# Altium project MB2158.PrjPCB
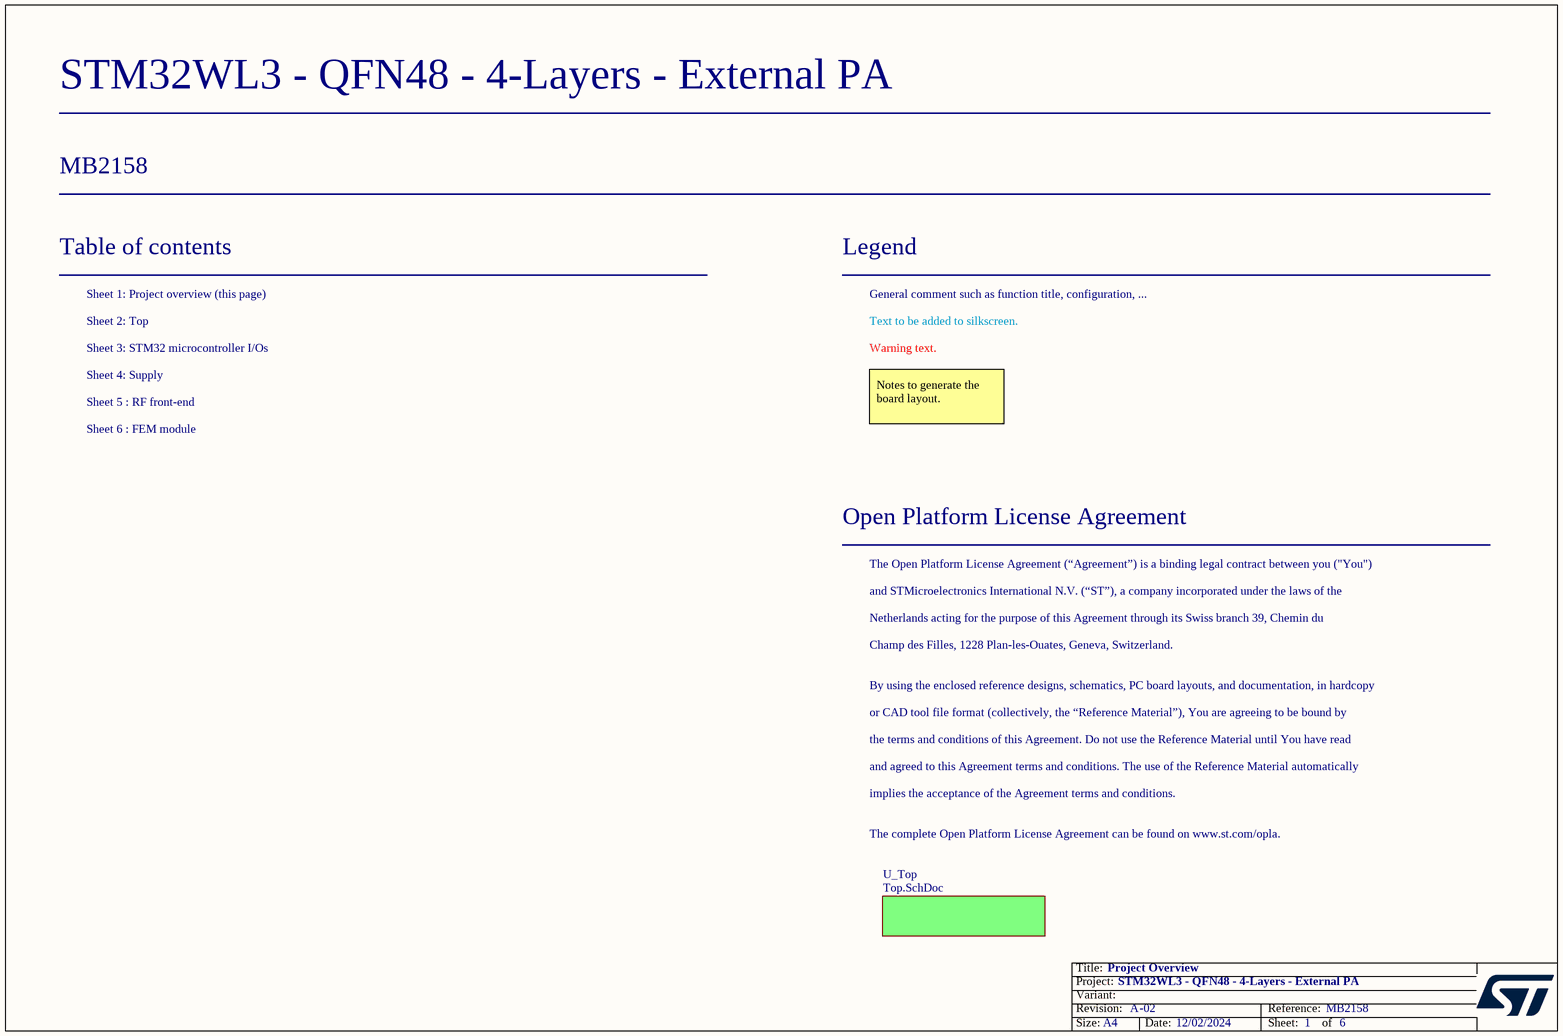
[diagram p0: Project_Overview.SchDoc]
Board_Assembly_Revision: 02; Board_Document_Date: 12/02/2024; Board_Name: STM32WL3 - QFN48 - 4-Layers - External PA; Board_PCB_Revision: A; Board_Reference: MB2158
6 sheets, 108 parts. Net scope: flat (ports and power ports of the same name join across sheets).
Board file: MB2158.PcbDoc
Sheets:
  Project_Overview.SchDoc
    U_Top = Top.SchDoc
      Designator = MCU_IOs.SchDoc
      Designator = RF.SchDoc
      Designator = Supply.SchDoc
      U_FEM = FEM.SchDoc

## Sheet Project_Overview.SchDoc: Project Overview
size A4; Date: Not used; ApprovedBy: Not used; CheckedBy: Not used; Author: Not used; CompanyName: STMicroelectronics; DrawnBy: Not used; Engineer: Not used; Organization: Not used; Address1: Not used; Address2: Not used; Address3: Not used; Address4: Not used; DocumentNumber: Not used; Revision: Not used; SheetNumber: 1; SheetTotal: 6

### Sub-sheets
U_Top = Top.SchDoc: no entries

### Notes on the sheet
- Table of contents
- Sheet 1: Project overview (this page)
- Legend
- General comment such as function title, configuration, ...
- Sheet 2: Top
- Sheet 3: STM32 microcontroller I/Os
- Sheet 4: Supply
- Text to be added to silkscreen.
- Warning text.
- Sheet 5 : RF front-end
- Sheet 6 : FEM module
- Notes to generate the board layout.
- Open Platform License Agreement
- The Open Platform License Agreement (“Agreement”) is a binding legal contract between you ("You")
- and STMicroelectronics International N.V. (“ST”), a company incorporated under the laws of the
- Netherlands acting for the purpose of this Agreement through its Swiss branch 39, Chemin du
- Champ des Filles, 1228 Plan-les-Ouates, Geneva, Switzerland.
- By using the enclosed reference designs, schematics, PC board layouts, and documentation, in hardcopy
- or CAD tool file format (collectively, the “Reference Material”), You are agreeing to be bound by
- the terms and conditions of this Agreement. Do not use the Reference Material until You have read
- and agreed to this Agreement terms and conditions. The use of the Reference Material automatically
- implies the acceptance of the Agreement terms and conditions.
- The complete Open Platform License Agreement can be found on www.st.com/opla.

## Sheet Top.SchDoc: Top Schematic
size A4; Date: Not used; ApprovedBy: Not used; CheckedBy: Not used; Author: Not used; CompanyName: STMicroelectronics; DrawnBy: Not used; Engineer: Not used; Organization: Not used; Address1: Not used; Address2: Not used; Address3: Not used; Address4: Not used; DocumentNumber: Not used; Revision: Not used; SheetNumber: 2; SheetTotal: 6
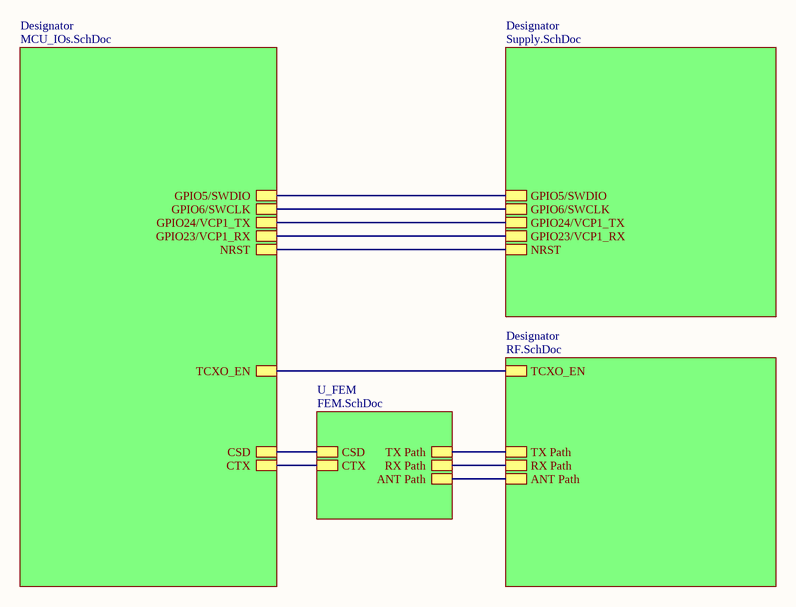
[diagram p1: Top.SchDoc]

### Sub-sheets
Designator = MCU_IOs.SchDoc: NRST, GPIO5/SWDIO, GPIO6/SWCLK, GPIO24/VCP1_TX, GPIO23/VCP1_RX, CTX, CSD, TCXO_EN
Designator = RF.SchDoc: RX Path, TX Path, ANT Path, TCXO_EN
Designator = Supply.SchDoc: NRST, GPIO5/SWDIO, GPIO6/SWCLK, GPIO23/VCP1_RX, GPIO24/VCP1_TX
U_FEM = FEM.SchDoc: TX Path, RX Path, CSD, CTX, ANT Path

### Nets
(unnamed): sheet Designator/NRST, sheet Designator/NRST
(unnamed): sheet Designator/GPIO5/SWDIO, sheet Designator/GPIO5/SWDIO  [a separate net that carries the same name]
(unnamed): sheet Designator/GPIO6/SWCLK, sheet Designator/GPIO6/SWCLK  [a separate net that carries the same name]
(unnamed): sheet Designator/GPIO24/VCP1_TX, sheet Designator/GPIO24/VCP1_TX  [a separate net that carries the same name]
(unnamed): sheet Designator/GPIO23/VCP1_RX, sheet Designator/GPIO23/VCP1_RX  [a separate net that carries the same name]
(unnamed): sheet Designator/CTX, sheet U_FEM/CTX  [a separate net that carries the same name]
(unnamed): sheet Designator/CSD, sheet U_FEM/CSD  [a separate net that carries the same name]
(unnamed): sheet Designator/TCXO_EN, sheet Designator/TCXO_EN  [a separate net that carries the same name]
(unnamed): sheet Designator/RX Path, sheet U_FEM/RX Path  [a separate net that carries the same name]
(unnamed): sheet Designator/TX Path, sheet U_FEM/TX Path  [a separate net that carries the same name]
(unnamed): sheet Designator/ANT Path, sheet U_FEM/ANT Path  [a separate net that carries the same name]

## Sheet MCU_IOs.SchDoc: STM32 I/Os & Clock
size A4; Date: Not used; ApprovedBy: Not used; CheckedBy: Not used; Author: Not used; CompanyName: STMicroelectronics; DrawnBy: Not used; Engineer: Not used; Organization: Not used; Address1: Not used; Address2: Not used; Address3: Not used; Address4: Not used; DocumentNumber: Not used; Revision: Not used; SheetNumber: 3; SheetTotal: 6
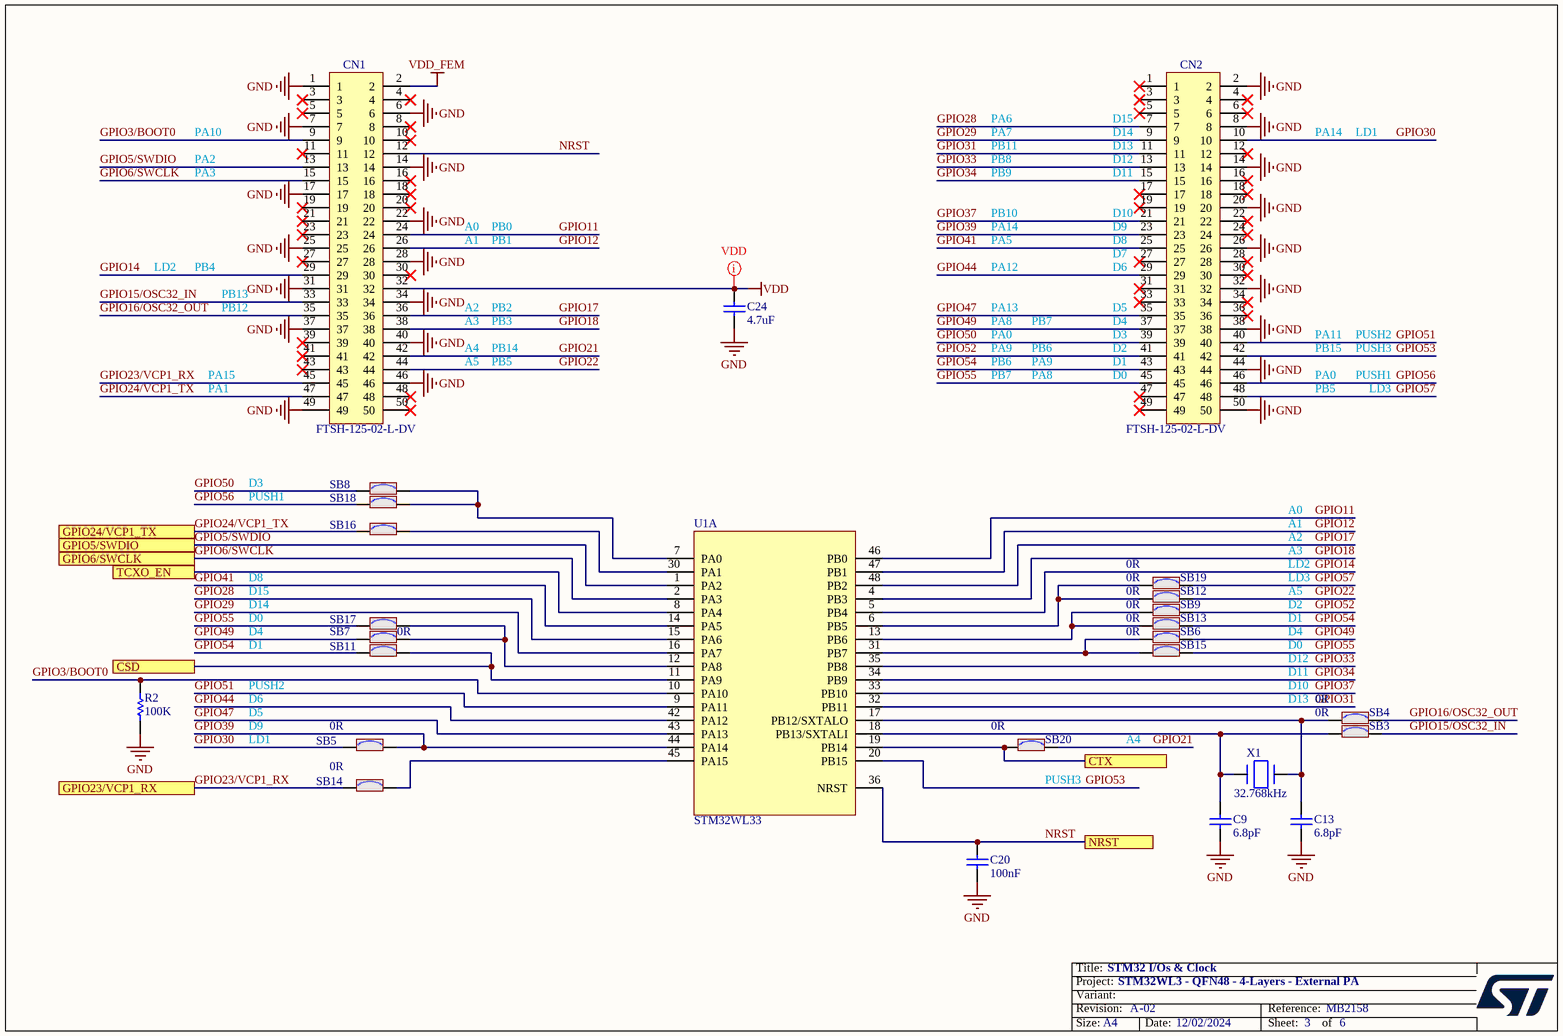
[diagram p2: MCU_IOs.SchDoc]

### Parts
C9  value 6.8pF  [C0402]  (hidden comment: Capacitor)
C13  value 6.8pF  [C0402]  (hidden comment: Capacitor)
C20  value 100nF  [C0402]  (hidden comment: Capacitor)
C24  value 4.7uF  [C0402]  (hidden comment: Capacitor)
CN1  FTSH-125-02-L-DV  [CON_SAMTEC_FTSH-125-02-L-DV]
CN2  FTSH-125-02-L-DV  [CON_SAMTEC_FTSH-125-02-L-DV]
R2  value 100K  [R0402]  (hidden comment: Resistor)
SB3  value 0R  [SOLDER-BRIDGE_R0402-0R]  (hidden comment: SB_ON)
SB4  value 0R  [SOLDER-BRIDGE_R0402-0R]  (hidden comment: SB_ON)
SB5  value 0R  [SOLDER-BRIDGE_R0402-0R]  (hidden comment: SB_ON)
SB6  value 0R  [SOLDER-BRIDGE_R0402-0R]  (hidden comment: SB_ON)
SB7  SB_ON  [SOLDER-BRIDGE_R0402-0R]  (value not drawn)
SB8  SB_ON  [SOLDER-BRIDGE_R0402-0R]  (value not drawn)
SB9  value 0R  [SOLDER-BRIDGE_R0402-0R]  (hidden comment: SB_ON)
SB11  value 0R  [SOLDER-BRIDGE_R0402-0R]  (hidden comment: SB_ON)
SB12  value 0R  [SOLDER-BRIDGE_R0402-0R]  (hidden comment: SB_ON)
SB13  value 0R  [SOLDER-BRIDGE_R0402-0R]  (hidden comment: SB_ON)
SB14  value 0R  [SOLDER-BRIDGE_R0402-0R]  (hidden comment: SB_ON)
SB15  value 0R  [SOLDER-BRIDGE_R0402-0R]  (hidden comment: SB_ON)
SB16  SB_ON  [SOLDER-BRIDGE_R0402-0R]  (value not drawn)
SB17  SB_ON  [SOLDER-BRIDGE_R0402-0R]  (value not drawn)
SB18  SB_ON  [SOLDER-BRIDGE_R0402-0R]  (value not drawn)
SB19  value 0R  [SOLDER-BRIDGE_R0402-0R]  (hidden comment: SB_ON)
SB20  value 0R  [SOLDER-BRIDGE_R0402-0R]  (hidden comment: SB_ON)
U1  STM32WL33  [ICC_QFN48-EPAD-4P5X4P5_6X6_P040]  (part A of 3)
X1  value 32.768kHz  [CRY_NX2012SA_2P]  (hidden comment: XTAL_2_PINS)

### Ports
CSD, CTX, GPIO5/SWDIO, GPIO6/SWCLK, GPIO23/VCP1_RX, GPIO24/VCP1_TX, NRST, TCXO_EN

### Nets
GND: C9.1 C13.1 C20.1 C24.1 CN1.1 CN1.6 CN1.7 CN1.14 CN1.17 CN1.22 CN1.25 CN1.28 CN1.31 CN1.34 CN1.37 CN1.40 CN1.46 CN1.49 CN2.2 CN2.8 CN2.14 CN2.20 CN2.26 CN2.32 CN2.38 CN2.44 CN2.50 R2.1
VDD: C24.2 CN1.32
VDD_FEM: CN1.2
CSD: SB11.2 U1.11(PA9) ; port CSD
CTX: SB20.1 U1.19(PB14) ; port CTX
GPIO3/BOOT0: CN1.9 R2.2 U1.10(PA10)
GPIO5/SWDIO: CN1.13 U1.1(PA2) ; port GPIO5/SWDIO
GPIO6/SWCLK: CN1.15 U1.2(PA3) ; port GPIO6/SWCLK
GPIO11: CN1.24 U1.46(PB0)
GPIO12: CN1.26 U1.47(PB1)
GPIO14: CN1.29 U1.5(PB4)
GPIO15/OSC32_IN: CN1.33 SB3.2
GPIO16/OSC32_OUT: CN1.35 SB4.2
GPIO17: CN1.36 U1.48(PB2)
GPIO18: CN1.38 U1.4(PB3)
GPIO21: CN1.42 SB20.2
GPIO22: CN1.44 SB12.2
GPIO23/VCP1_RX: CN1.45 SB14.1 ; port GPIO23/VCP1_RX
GPIO24/VCP1_TX: CN1.47 SB16.1 ; port GPIO24/VCP1_TX
GPIO28: CN2.7 U1.15(PA6)
GPIO29: CN2.9 U1.16(PA7)
GPIO30: CN2.10 SB5.1
GPIO31: CN2.11 U1.32(PB11)
GPIO33: CN2.13 U1.35(PB8)
GPIO34: CN2.15 U1.34(PB9)
GPIO37: CN2.21 U1.33(PB10)
GPIO39: CN2.23 SB5.2 U1.44(PA14)
GPIO41: CN2.25 U1.14(PA5)
GPIO44: CN2.29 U1.42(PA12)
GPIO47: CN2.35 U1.43(PA13)
GPIO49: CN2.37 SB6.2 SB7.1
GPIO50: CN2.39 SB8.1
GPIO51: CN2.40 U1.9(PA11)
GPIO52: CN2.41 SB9.2
GPIO53: CN2.42 U1.20(PB15)
GPIO54: CN2.43 SB11.1 SB13.2
GPIO55: CN2.45 SB15.2 SB17.1
GPIO56: CN2.46 SB18.1
GPIO57: CN2.48 SB19.2
NRST: C20.2 CN1.12 U1.36(NRST) ; port NRST
TCXO_EN: U1.8(PA4) ; port TCXO_EN
NetC9_2: C9.2 SB3.1 U1.18(PB13/SXTALI) X1.2(X2)
NetC13_2: C13.2 SB4.1 U1.17(PB12/SXTALO) X1.1(X1)
NetSB6_1: SB6.1 SB15.1 U1.31(PB7)
NetSB7_2: SB7.2 SB17.2 U1.12(PA8)
NetSB8_2: SB8.2 SB18.2 U1.7(PA0)
NetSB9_1: SB9.1 SB13.1 U1.13(PB6)
NetSB12_1: SB12.1 SB19.1 U1.6(PB5)
NetSB14_2: SB14.2 U1.45(PA15)
NetSB16_2: SB16.2 U1.30(PA1)

Not connected (* = marked no-connect by the designer): CN1 3* 4* 5* 8* 10* 11* 16* 18* 19* 20* 21* 23* 27* 30* 39* 41* 43* 48* 50*; CN2 1* 3* 4* 5* 6* 12* 16* 17* 18* 19* 22* 24* 27* 28* 30* 31* 33* 34* 36* 47* 49*

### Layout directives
net class VDD: VDD

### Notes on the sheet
- PA10
- PA2
- PA3
- PA7
- PA6
- PB8
- PB11
- PB9
- (near CN2) D11
- (near CN2) D13
- (near CN2) D14
- (near CN2) D15
- (near CN2) D12
- PA14
- LD1
- A0
- A1
- PB1
- PB0
- PA5
- PB10
- (near CN2) D10
- (near CN2) D9
- (near CN2) D8
- LD2
- PB4
- PB13
- PB12
- A2
- PB2
- PA13
- PA12
- (near CN2) D7
- (near CN2) D6
- (near CN2) D5
- PA15
- A5
- A4
- A3
- PB5
- PB14
- PB3
- PB7
- PB6
- PA0
- PA9
- PA8
- (near CN2) D1
- (near CN2) D4
- (near CN2) D3
- (near CN2) D2
- (near CN2) D0
- PA11
- PB15
- PUSH1
- PUSH2
- PUSH3
- PA1
- LD3
- D3
- D8
- D14
- D15
- D1
- D0
- D4
- D2
- D6
- D5
- D10
- D12
- D11
- D13
- D9
- (near SB20) PUSH3

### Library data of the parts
C9 C13 = MCD-03452: Capacitor, MLCC, 6.8pF, 50V,C0G/NP0, +/-0.05pF, 0402, T=0.5mm; Part_Preference: Recommended; Manufacturer: MURATA; Manufacturer_Part_Number: GJM1555C1H6R8WB01; ShowFields: YES; ID: 5568; Component_Country_Of_Origin: Japan, Singapore
C20 = MCD-00006: Capacitor, MLCC, 100nF, 16V, X7R, +/-10%, 0402, T=0.5mm; Manufacturer_Part_Number: CC0402KRX7R7BB104; Manufacturer: YAGEO; Part_Preference: Recommended; Partial_Alternate_Internal_Part_Number: MCD-03299; Order_Code_RS: 9402047; Component_Country_Of_Origin: China; ShowFields: YES; ID: 2474
C24 = MCD-03431: Capacitor, MLCC, 4.7uF, X5R, 10 V, 0402, ± 20%, T=0.5mm; Part_Preference: Recommended; Manufacturer: MURATA; Manufacturer_Part_Number: GRM155R61A475MEAAD; Order_Code_RS: 172-6870; ShowFields: YES; ID: 5547
CN1 CN2 = MCD-02746: Header, 25x2, 12.7mm, VR, SMD, T=4.83mm; Part_Type: Connector; Part_Preference: Recommended; Manufacturer: SAMTEC; Value: Header 25x2; ShowFields: YES; ID: 4858; Component_Country_Of_Origin: China, Costa Rica, Malaysia, USA, Vietnam
R2 = MCD-00059: Resistor, 100K, 0402, +/-1%, 1/16W; Part_Preference: Recommended; Manufacturer: YAGEO; Manufacturer_Part_Number: RC0402FR-07100KL; Partial_Alternate_Internal_Part_Number: MCD-03301; Order_Code_RS: 2421891; Component_Country_Of_Origin: China; ShowFields: YES; ID: 2533
SB3-SB6 SB8 SB9 SB11-SB20 = MCD-01618: Resistor, 0R, SB0402, 5%, 0.063W; Part_Preference: Recommended; Manufacturer: YAGEO; Manufacturer_Part_Number: RC0402JR-070RL; Order_Code_RS: 618-5804; Component_Country_Of_Origin: China; ShowFields: YES; ID: 3718
SB7 = MCD-01618: Solder Bridge 0402 ON; Part_Type: Misc; Part_Preference: Recommended; Manufacturer: YAGEO; Manufacturer_Part_Number: RC0402JR-070RL; Order_Code_RS: 618-5804; Component_Country_Of_Origin: China
U1 = MCD-03488: IC, Programmable Sub-1GHz wireless SoC; Part_Preference: Recommended; Manufacturer: STMICROELECTRONICS; Manufacturer_Part_Number: STM32WL33CCV6UTR; Component_Country_Of_Origin: Unknown; ShowFields: YES; ID: 5604
X1 = MCD-01445: Crystal, 32.768kHz, 7pF, +/-20ppm, 80K, 2.05x1.2mm; BMS_Part_Number: 9157043; Part_Type: Crystal_Osc; Part_Preference: Recommended; Manufacturer: NDK; Manufacturer_Part_Number: NX2012SA-32.768KHz-EXS00A-MU00389; Component_Country_Of_Origin: Japan; ShowFields: YES; ID: 3545

## Sheet RF.SchDoc: STM32 RF
size A4; Date: Not used; ApprovedBy: Not used; CheckedBy: Not used; Author: Not used; CompanyName: STMicroelectronics; DrawnBy: Not used; Engineer: Not used; Organization: Not used; Address1: Not used; Address2: Not used; Address3: Not used; Address4: Not used; DocumentNumber: Not used; Revision: Not used; SheetNumber: 5; SheetTotal: 6
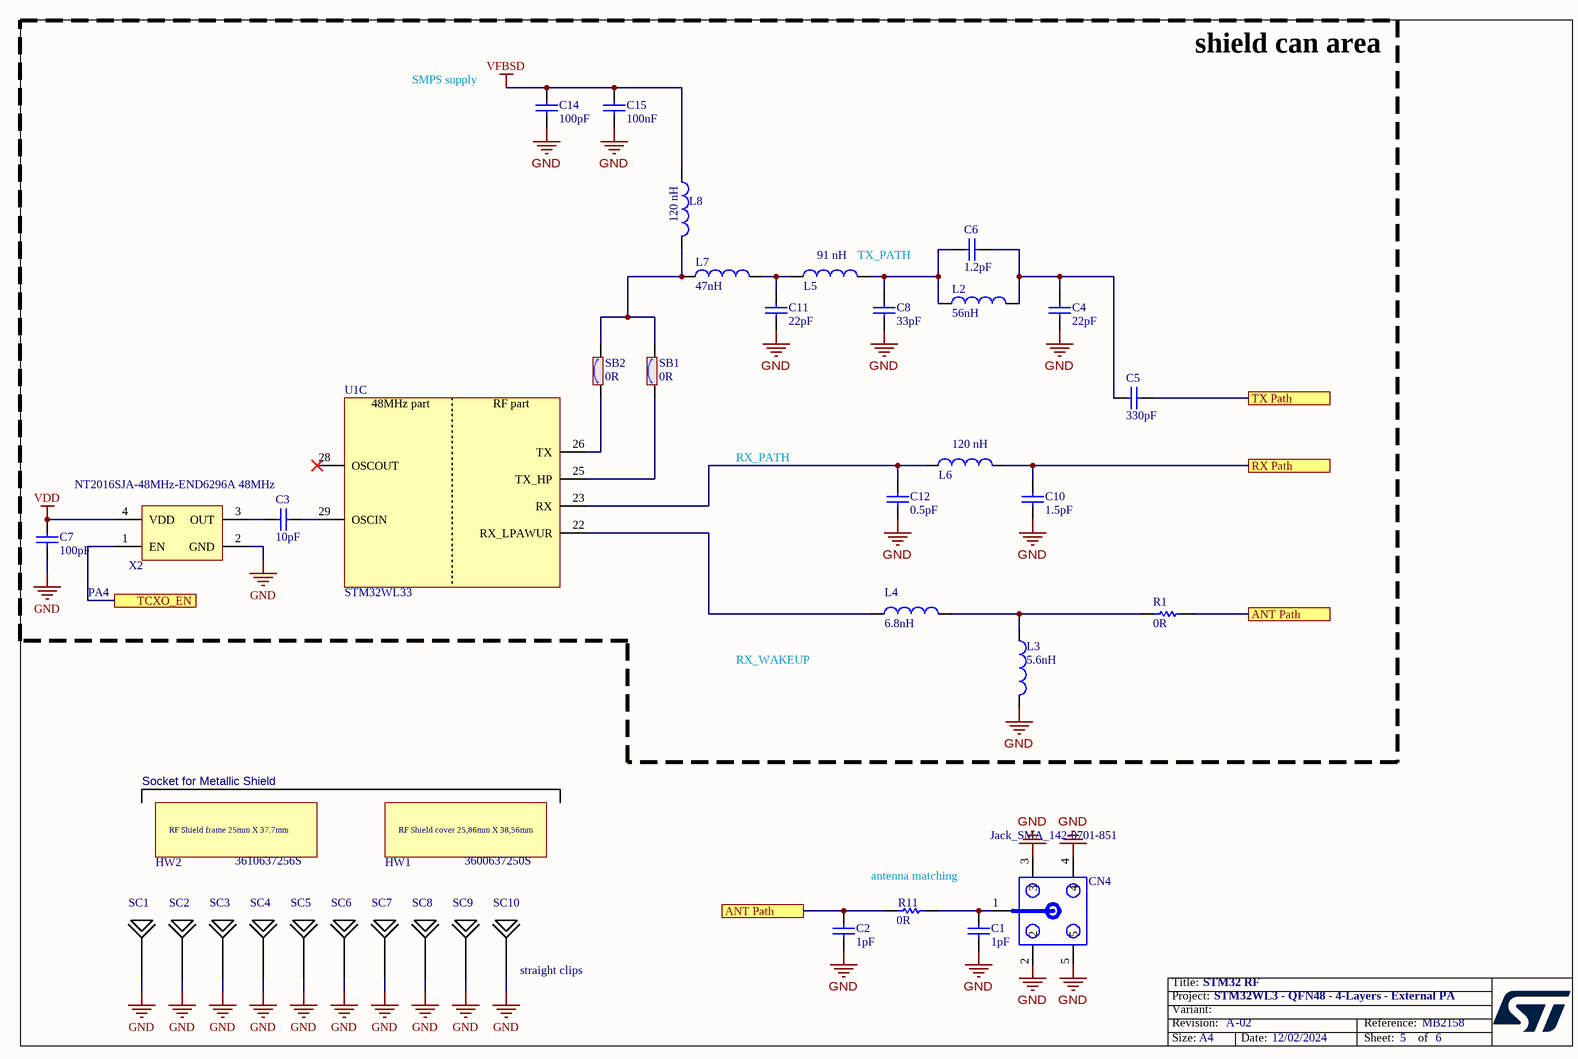
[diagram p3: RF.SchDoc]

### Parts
C1  value 1pF  [C0402]  (hidden comment: Capacitor)
C2  value 1pF  [C0402]  (hidden comment: Capacitor)
C3  value 10pF  [C0402]  (hidden comment: Capacitor)
C4  value 22pF  [C0402_H0P5]  (hidden comment: Capacitor)
C5  value 330pF  [C0402]  (hidden comment: Capacitor)
C6  value 1.2pF  [C0402]  (hidden comment: Capacitor)
C7  value 100pF  [C0402]  (hidden comment: Capacitor)
C8  value 33pF  [C0402]  (hidden comment: Capacitor)
C10  value 1.5pF  [C0402]  (hidden comment: Capacitor)
C11  value 22pF  [C0402_H0P5]  (hidden comment: Capacitor)
C12  value 0.5pF  [C0402]  (hidden comment: Capacitor)
C14  value 100pF  [C0402]  (hidden comment: Capacitor)
C15  value 100nF  [C0402]  (hidden comment: Capacitor)
CN4  value Jack_SMA_142-0701-851  [CON_SMA-RF_CINCH_142-0701-851]  (hidden comment: mmcx)
HW1  3600637250S  [3600637250S]
HW2  3610637256S  [3610637256S]
L2  value 56nH  [IND_0402_MURATA_LQW15AN_H0P5]  (hidden comment: Inductor)
L3  value 5.6nH  [IND_0402_MURATA_LQG15HSXXXX02_H0P5]  (hidden comment: Inductor)
L4  value 6.8nH  [IND_0402_MURATA_LQG15HSXXXX02_H0P5]  (hidden comment: Inductor)
L5  value 91 nH  [LQG15WZ91NJ02D]  (hidden comment: LQG15WZ91NJ02D)
L6  value 120 nH  [LQG15HSR12J02D]  (hidden comment: LQG15HSR12J02D)
L7  value 47nH  [IND_0402_MURATA_LQG15HSXXXX02_H0P5]  (hidden comment: Inductor)
L8  value 120 nH  [LQG15HSR12J02D]  (hidden comment: LQG15HSR12J02D)
R1  value 0R  [R0402]  (hidden comment: Resistor)
R11  value 0R  [R0402]  (hidden comment: Resistor)
SB1  value 0R  [SOLDER-BRIDGE_R0201_0R]  (hidden comment: SB_ON)
SB2  value 0R  [SOLDER-BRIDGE_R0201_0R]  (hidden comment: SB_ON)
SC1  36900000  [36900000]  (value not drawn)
SC2  36900000  [36900000]  (value not drawn)
SC3  36900000  [36900000]  (value not drawn)
SC4  36900000  [36900000]  (value not drawn)
SC5  36900000  [36900000]  (value not drawn)
SC6  36900000  [36900000]  (value not drawn)
SC7  36900000  [36900000]  (value not drawn)
SC8  36900000  [36900000]  (value not drawn)
SC9  36900000  [36900000]  (value not drawn)
SC10  36900000  [36900000]  (value not drawn)
U1  STM32WL33  [ICC_QFN48-EPAD-4P5X4P5_6X6_P040]  (part C of 3)
X2  value NT2016SJA-48MHz-END6296A 48MHz  [CRY_NDK_NT2016SA_4P]  (hidden comment: IC_NT2016S)

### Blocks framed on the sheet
shield can area: C3-C8 C10-C12 C14 C15 L2-L8 R1 SB1 SB2 U1 X2

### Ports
ANT Path, RX Path, TCXO_EN, TX Path

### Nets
GND: C1.1 C2.1 C4.1 C7.1 C8.1 C10.1 C11.1 C12.1 C14.1 C15.1 CN4.2 CN4.3 CN4.4 CN4.5 L3.1 SC1.1 SC2.1 SC3.1 SC4.1 SC5.1 SC6.1 SC7.1 SC8.1 SC9.1 SC10.1 X2.2(GND)
VDD: C7.2 X2.4(VDD)
VFBSD: C14.2 C15.2 L8.1
ANT Path: C2.2 R1.2 R11.1 ; port ANT Path
RX Path: C10.2 L6.2 ; port RX Path
TCXO_EN: X2.1(EN) ; port TCXO_EN
TX Path: C5.2 ; port TX Path
NetC1_2: C1.2 CN4.1 R11.2
NetC3_1: C3.1 X2.3(OUT)
NetC3_2: C3.2 U1.29(OSCIN)
NetC4_2: C4.2 C5.1 C6.2 L2.2
NetC6_1: C6.1 C8.2 L2.1 L5.2
NetC11_2: C11.2 L5.1 L7.2
NetC12_2: C12.2 L6.1 U1.23(RX)
NetL3_2: L3.2 L4.2 R1.1
NetL4_1: L4.1 U1.22(RX_LPAWUR)
NetL7_1: L7.1 L8.2 SB1.2 SB2.2
NetSB1_1: SB1.1 U1.25(TX_HP)
NetSB2_1: SB2.1 U1.26(TX)

Not connected (* = marked no-connect by the designer): U1 28(OSCOUT)*

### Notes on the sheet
- SMPS supply
- (near L5) TX_PATH
- RX_PATH
- PA4
- RX_WAKEUP
- (near HW2) Socket for Metallic Shield
- antenna matching
- (near SC10) straight clips

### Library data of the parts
C1 C2 = MCD-01600: Capacitor, MLCC, 1pF, 50V, C0G/NP0, +/-0.1pF, 0402, T=0.5mm; Part_Preference: Recommended; Manufacturer: YAGEO; Manufacturer_Part_Number: CC0402BRNPO9BN1R0; Component_Country_Of_Origin: China; ShowFields: YES; ID: 3700
C3 = MCD-03237: Capacitor, MLCC, 10pF, 50V, C0G/NP0, +/-5%, 0402, T=0.55mm; Part_Preference: Recommended; Manufacturer: MURATA; Manufacturer_Part_Number: GRM1555C1H100JA01; Component_Country_Of_Origin: China, Japan; ShowFields: YES; ID: 5353
C4 C11 = MCD-03948: Capacitor, MLCC, 22pF, 50V, C0G/NP0, +/-5%, 0402, T=0.5mm; Part_Preference: Recommended; Manufacturer: MURATA; Manufacturer_Part_Number: GJM1555C1H220JB01; Order_Code_RS: 185-3422; Component_Country_Of_Origin: Japan, Singapore; ShowFields: YES; ID: 6064
C5 = MCD-01579: Capacitor, MLCC, 330pF, 50V, C0G/NP0, +/-5%, 0402, T=0.5mm; Part_Preference: Recommended; Manufacturer: YAGEO; Manufacturer_Part_Number: CC0402JRNPO9BN331; Component_Country_Of_Origin: China; ShowFields: YES; ID: 3679
C6 = MCD-02065: Capacitor, MLCC, 1.2pF, 50V, C0G/NP0, 0.05pf, 0402, T=0.5mm; Part_Preference: Recommended; Manufacturer: MURATA; Manufacturer_Part_Number: GJM1555C1H1R2WB01; Order_Code_RS: 846-7246; Component_Country_Of_Origin: Japan°°; ShowFields: YES; ID: 4165
C7 C14 = MCD-00205: Capacitor, MLCC, 100pF, 50V, C0G/NP0, +/-5%, 0402, T=0.5mm; Part_Preference: Recommended; Manufacturer: YAGEO; Manufacturer_Part_Number: CC0402JRNPO9BN101; Component_Country_Of_Origin: China; ShowFields: YES; ID: 2658
C8 = MCD-01784: Capacitor, MLCC, 33pF, 50V, C0G/NP0, +/-2%, 0402, T=0.5mm; BMS_Part_Number: 9142008; Part_Preference: Recommended; Manufacturer: YAGEO; Manufacturer_Part_Number: CC0402GRNPO9BN330; Component_Country_Of_Origin: China; ShowFields: YES; ID: 3884
C10 = MCD-02994: Capacitor, MLCC, 1.5pF, 50V, C0G/NP0, +/-0.25pF, 0402, T=0.5mm; Part_Preference: Recommended; Manufacturer: MURATA; Manufacturer_Part_Number: GRM1555C1H1R5CA01; Component_Country_Of_Origin: Japan°; ShowFields: YES; ID: 5110
C12 = MCD-02215: Capacitor, MLCC, 0.5pF, 50V, C0G/NP0, +/-0.1pF, 0402, T=0.5mm; Part_Preference: Recommended; Manufacturer: MURATA; Manufacturer_Part_Number: GJM1555C1HR50BB01; Order_Code_RS: 723-5111P; Component_Country_Of_Origin: Japan°°; ShowFields: YES; ID: 4315
C15 = MCD-03442: Capacitor, MLCC, 100nF, 25V, X7R, +/-10%, 0402, T=0.5mm; Part_Preference: Recommended; Manufacturer: MURATA; Manufacturer_Part_Number: GRM155R71E104KE14; Order_Code_RS: 247-8011; ShowFields: YES; ID: 5558; Component_Country_Of_Origin: China, Japan, Philippines, Singapore
CN4 = MCD-02072: Jack_SMA, VR, PCB edge, 50R, T=7.92mm; Part_Type: Connector; Part_Preference: Recommended; Manufacturer: CINCH; Manufacturer_Part_Number: 142-0701-851; Order_Code_RS: 885-7532; Component_Country_Of_Origin: USA°°; ShowFields: YES; ID: 4172
HW1 = 3600637250S: 3600637250S shield cover; Internal_Part_Number: MCD-05006; Part_Preference: Recommended
HW2 = 3610637256S: 3610637256S shield frame; Internal_Part_Number: MCD-05007; Part_Preference: Recommended
L2 = MCD-02074: Inductor, 56nH, +/-0.2nH, Itemp=200mA max, 1R17, 0402, T=0.6mm, Qmin=25; Part_Preference: Recommended; Manufacturer: MURATA; Manufacturer_Part_Number: LQW15AN56NG00; Order_Code_RS: 166-9771; Component_Country_Of_Origin: Japan°°; ShowFields: YES; ID: 4174
L3 = MCD-03462: Inductor, 5.6nH, +/-0.3nH, 0.65A, 180mR, 0402, T=0.5mm; Part_Preference: Recommended; Manufacturer: MURATA; Manufacturer_Part_Number: LQG15HS5N6S02; Order_Code_RS: 124-8165P; Component_Country_Of_Origin: Japan; ShowFields: YES; ID: 5578
L4 = MCD-03461: Inductor, 6.8nH, +/-3%, 0.6A, 220mR, 0402, T=0.5mm; Manufacturer: MURATA; Manufacturer_Part_Number: LQG15HS6N8H02; Part_Preference: Recommended; Component_Country_Of_Origin: Japan; ShowFields: YES; ID: 5577
L5 = LQG15WZ91NJ02D: Internal_Part_Number: MCD-05042; Part_Preference: Recommended
L6 = LQG15HSR12J02D: Internal_Part_Number: MCD-05043; Part_Preference: Recommended
L7 = MCD-02075: Inductor, 47nH, +/-2%, Itemp=210mA max, 0R108, 0402, T=0.6mm, Qmin=30; Part_Preference: Recommended; Manufacturer: MURATA; Manufacturer_Part_Number: LQW15AN47NG00; Order_Code_RS: 792-6445; Component_Country_Of_Origin: Japan°°; ShowFields: YES; ID: 4175
L8 = LQG15HSR12J02D: 120nH; Internal_Part_Number: MCD-05043; Part_Preference: Recommended
R1 R11 = MCD-00052: Resistor, 0R, 0402, +/-5%, 1/16W; Part_Preference: Recommended; Manufacturer: YAGEO; Manufacturer_Part_Number: RC0402JR-070RL; Order_Code_RS: 9232516RL; Component_Country_Of_Origin: China; ShowFields: YES; ID: 2540
SB1 SB2 = MCD-03219: Solder Bridge ON, 0R, 0201, 1/20W; Part_Type: Misc; Part_Preference: Recommended; Manufacturer: YAGEO; Manufacturer_Part_Number: RC0201JR-070RL; Order_Code_RS: 198-7623; Component_Country_Of_Origin: China; ShowFields: YES; ID: 5335
SC1-SC10 = 36900000: 36900000 Shield clip; Internal_Part_Number: MCD-05008; Part_Preference: Recommended
U1 = MCD-03488: as U1 on sheet MCU_IOs
X2 = MCD-04329: Oscillator, TCXO, 48MHz, +/-5ppm, clipped sine wave, 3V3, 2x1.6mm; Part_Type: Crystal_Osc; Part_Preference: Recommended; Manufacturer: NDK; Manufacturer_Part_Number: NT2016SJA-48MHz-END6296A; Component_Country_Of_Origin: Unknown; ShowFields: YES; ID: 6445

## Sheet Supply.SchDoc: STM32 power
size A4; Date: Not used; ApprovedBy: Not used; CheckedBy: Not used; Author: Not used; CompanyName: STMicroelectronics; DrawnBy: Not used; Engineer: Not used; Organization: Not used; Address1: Not used; Address2: Not used; Address3: Not used; Address4: Not used; DocumentNumber: Not used; Revision: Not used; SheetNumber: 4; SheetTotal: 6
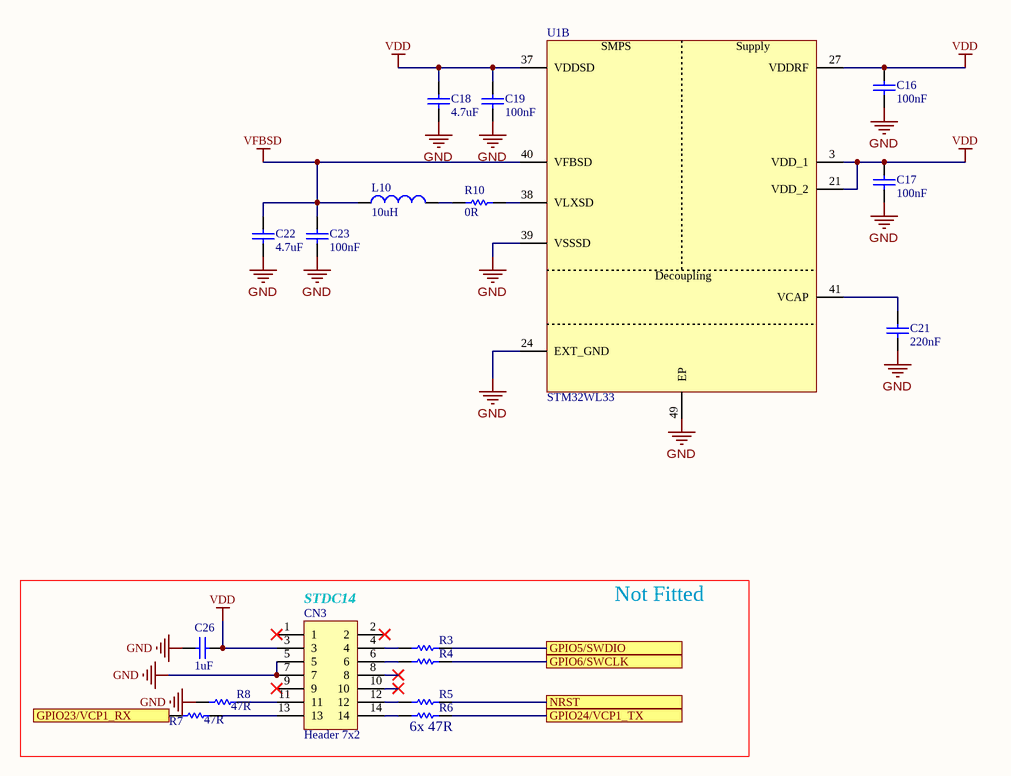
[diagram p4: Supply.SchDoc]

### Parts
C16  value 100nF  [C0402]  (hidden comment: Capacitor)
C17  value 100nF  [C0402]  (hidden comment: Capacitor)
C18  value 4.7uF  [C0402]  (hidden comment: Capacitor)
C19  value 100nF  [C0402]  (hidden comment: Capacitor)
C21  value 220nF  [C0402]  (hidden comment: Capacitor)
C22  value 4.7uF  [C0402]  (hidden comment: Capacitor)
C23  value 100nF  [C0402]  (hidden comment: Capacitor)
C26  value 1uF  [C0603]  (hidden comment: Capacitor)
CN3  Header 7x2  [CON_SAMTEC_FTSH-107-01-L-DV-K]
L10  value 10uH  [IND_0805_MURATA_LQM21]  (hidden comment: Inductor)
R3  Resistor  [R0402]  (value not drawn)
R4  Resistor  [R0402]  (value not drawn)
R5  Resistor  [R0402]  (value not drawn)
R6  Resistor  [R0402]  (value not drawn)
R7  value 47R  [R0402]  (hidden comment: Resistor)
R8  value 47R  [R0402]  (hidden comment: Resistor)
R10  value 0R  [R0402]  (hidden comment: Resistor)
U1  STM32WL33  [ICC_QFN48-EPAD-4P5X4P5_6X6_P040]  (part B of 3)

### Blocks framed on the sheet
Not Fitted: C26 CN3 R3-R8

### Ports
GPIO5/SWDIO, GPIO6/SWCLK, GPIO23/VCP1_RX, GPIO24/VCP1_TX, NRST

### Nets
GND: C16.1 C17.1 C18.1 C19.1 C21.1 C22.1 C23.2 C26.1 CN3.5 CN3.7 R8.1 U1.24(EXT_GND) U1.39(VSSSD) U1.49(EP)
VDD: C16.2 C17.2 C18.2 C19.2 C26.2 CN3.3 U1.3(VDD_1) U1.21(VDD_2) U1.27(VDDRF) U1.37(VDDSD)
VFBSD: C22.2 C23.1 L10.1 U1.40(VFBSD)
GPIO5/SWDIO: R3.2 ; port GPIO5/SWDIO
GPIO6/SWCLK: R4.2 ; port GPIO6/SWCLK
GPIO23/VCP1_RX: R7.1 ; port GPIO23/VCP1_RX
GPIO24/VCP1_TX: R6.2 ; port GPIO24/VCP1_TX
NRST: R5.2 ; port NRST
NetC21_2: C21.2 U1.41(VCAP)
NetCN3_4: CN3.4 R3.1
NetCN3_6: CN3.6 R4.1
NetCN3_11: CN3.11 R8.2
NetCN3_12: CN3.12 R5.1
NetCN3_13: CN3.13 R7.2
NetCN3_14: CN3.14 R6.1
NetL10_2: L10.2 R10.1
NetR10_2: R10.2 U1.38(VLXSD)

Not connected (* = marked no-connect by the designer): CN3 1* 2* 8* 9* 10*

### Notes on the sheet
- (near CN3) STDC14
- (near R6) 6x 47R

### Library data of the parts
C16 C17 C19 C23 = MCD-03442: as C15 on sheet RF
C18 C22 = MCD-03431: Capacitor, MLCC, 4.7uF, 10V, X5R, +/-20%, 0402, T=0.5mm; Part_Preference: Recommended; Manufacturer: MURATA; Manufacturer_Part_Number: GRM155R61A475MEAA; Order_Code_RS: 172-6870; ShowFields: YES; ID: 5547; Component_Country_Of_Origin: China, Japan, Philippines, Singapore
C21 = MCD-03077: Capacitor, MLCC, 220nF, 35V, X6S, 10%, 0402, T=0.5mm; Part_Preference: Recommended; Manufacturer: MURATA; Manufacturer_Part_Number: GRM155C8YA224KE01; Component_Country_Of_Origin: Japan; ShowFields: YES; ID: 5193
C26 = MCD-00010: Capacitor, MLCC, 1uF, 16V, X5R, +/-10%, 0603, T=0.8mm; Manufacturer_Part_Number: CC0603KRX5R7BB105; Manufacturer: YAGEO; Part_Preference: Recommended; Order_Code_RS: 2370680; Component_Country_Of_Origin: China; ShowFields: YES; ID: 2470
CN3 = MCD-01531: Header, 7x2, 1.27mm, VR, T=5.97mm, FTSH series STDC14 without Alignment Pin; Part_Type: Connector; Part_Preference: Recommended; Manufacturer: SAMTEC; Manufacturer_Part_Number: FTSH-107-01-L-DV-K; Order_Code_RS: 179-9021; Component_Country_Of_Origin: China, Costa Rica, Malaysia, USA, Vietnam; ShowFields: YES; ID: 3631
L10 = MCD-02317: Inductor, 10uH, +/-20%, 100mA, 0R5, 0805, T=1.45mm; Part_Preference: Recommended; Manufacturer: MURATA; Manufacturer_Part_Number: LQM21FN100M80L; Order_Code_RS: 786-7074; Component_Country_Of_Origin: Japan°°; ShowFields: YES; ID: 4423
R3-R8 = MCD-00481: Resistor, 47R, 0402, +/-1%, 1/16W; Manufacturer_Part_Number: RC0402FR-0747RL; Manufacturer: YAGEO; Part_Preference: Recommended; Component_Country_Of_Origin: China; ShowFields: YES; ID: 2796
R10 = MCD-00052: as R1 on sheet RF
U1 = MCD-03488: as U1 on sheet MCU_IOs

## Sheet FEM.SchDoc: FEM Module
size A4; Board_Assembly_Revision: 02; Date: Not used; ApprovedBy: Not used; CheckedBy: Not used; Author: Not used; CompanyName: STMicroelectronics; DrawnBy: Not used; Engineer: Not used; Organization: Not used; Address1: Not used; Address2: Not used; Address3: Not used; Address4: Not used; DocumentNumber: Not used; Revision: Not used; SheetNumber: 6; SheetTotal: 6
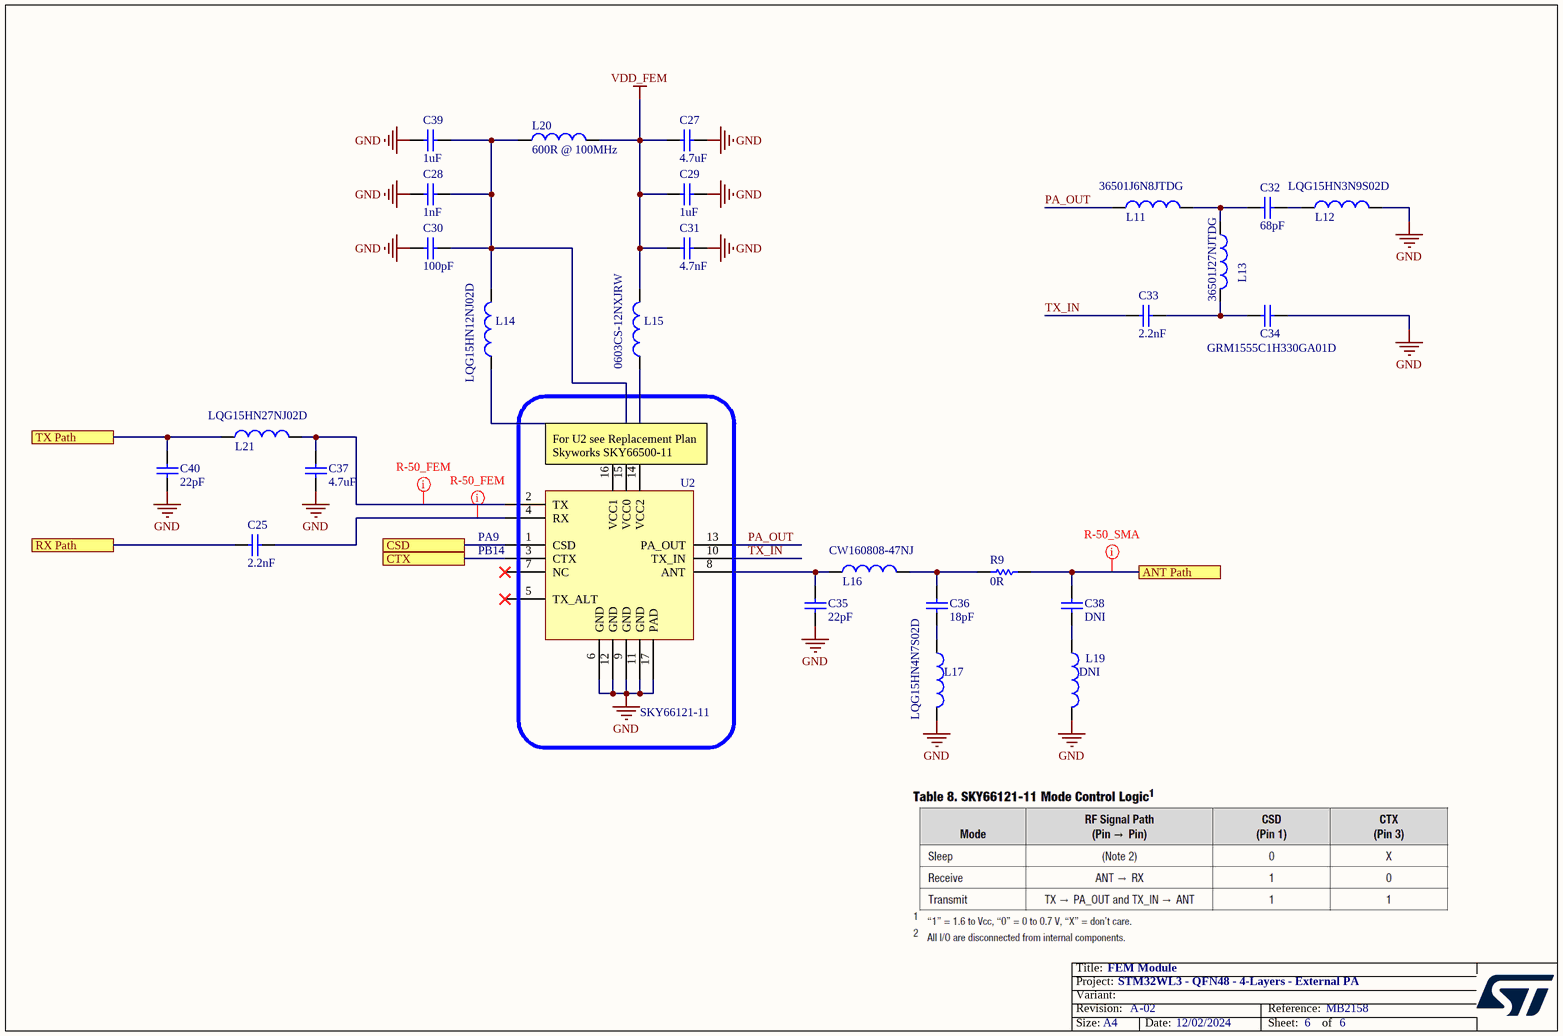
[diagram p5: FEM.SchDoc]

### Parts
C25  value 2.2nF  [C0402]  (hidden comment: Capacitor)
C27  value 4.7uF  [C0603_MURATA_GRM18_H0P5]  (hidden comment: Capacitor)
C28  value 1nF  [C0402]  (hidden comment: Capacitor)
C29  value 1uF  [C0402_H0P5]  (hidden comment: Capacitor)
C30  value 100pF  [C0402]  (hidden comment: Capacitor)
C31  value 4.7nF  [C0402_MURATA_GJM-GRM15_H0P5]  (hidden comment: Capacitor)
C32  value 68pF  [C0402_MURATA_GRM155_H0P5]  (hidden comment: Capacitor)
C33  value 2.2nF  [C0402]  (hidden comment: Capacitor)
C34  GRM1555C1H330GA01D  [GJM1555C1HR70WB01D]
C35  value 22pF  [C0402_H0P5]  (hidden comment: Capacitor)
C36  value 18pF  [C0402_MURATA_GJM155_H0P5]  (hidden comment: Capacitor)
C37  value 4.7uF  [C0402]  (hidden comment: Capacitor)
C38  value DNI  [C0402]  (hidden comment: Capacitor)
C39  value 1uF  [C0402_H0P5]  (hidden comment: Capacitor)
C40  value 22pF  [C0402_H0P5]  (hidden comment: Capacitor)
L11  36501J6N8JTDG  [36501J6N8JTDG]
L12  LQG15HN3N9S02D  [LQG15HN3N9S02D]
L13  36501J27NJTDG  [36501J27NJTDG]
L14  LQG15HN12NJ02D  [LQG15HN12NJ02D]
L15  0603CS-12NXJRW  [0603CS-12NXJRW]
L16  CW160808-47NJ  [CW160808-47NJ]
L17  LQG15HN4N7S02D  [LQG15HN4N7S02D]
L19  value DNI  [L0402]  (hidden comment: Inductor)
L20  value 600R @ 100MHz  [IND_0402_MURATA_BLM15H_H0P5]  (hidden comment: BEAD)
L21  LQG15HN27NJ02D  [LQG15HN12NJ02D]
R9  value 0R  [R0402]  (hidden comment: Resistor)
U2  SKY66121-11  [SKY65367-11]

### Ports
ANT Path, CSD, CTX, RX Path, TX Path

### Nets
GND: C27.2 C28.1 C29.2 C30.1 C31.2 C34.2 C35.1 C37.1 C39.1 C40.1 L12.2 L17.1 L19.2 U2.6(GND) U2.9(GND) U2.11(GND) U2.12(GND) U2.17(PAD)
VDD_FEM: C27.1 C29.1 C31.1 L15.2 L20.2
ANT Path: C38.2 R9.2 ; port ANT Path
CSD: U2.1(CSD) ; port CSD
CTX: U2.3(CTX) ; port CTX
PA_OUT: L11.1 U2.13(PA_OUT)
RX Path: C25.1 ; port RX Path
TX Path: C40.2 L21.1 ; port TX Path
TX_IN: C33.1 U2.10(TX_IN)
NetC25_2: C25.2 U2.4(RX)
NetC28_2: C28.2 C30.2 C39.2 L14.2 L20.1 U2.15(VCC0)
NetC32_1: C32.1 L11.2 L13.1
NetC32_2: C32.2 L12.1
NetC33_2: C33.2 C34.1 L13.2
NetC35_2: C35.2 L16.1 U2.8(ANT)
NetC36_1: C36.1 L17.2
NetC36_2: C36.2 L16.2 R9.1
NetC37_2: C37.2 L21.2 U2.2(TX)
NetC38_1: C38.1 L19.1
NetL14_1: L14.1 U2.16(VCC1)
NetL15_1: L15.1 U2.14(VCC2)

Not connected (* = marked no-connect by the designer): U2 5(TX_ALT)* 7(NC)*

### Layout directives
mark named R-50_FEM: NetC25_2, NetC37_2
mark named R-50_SMA: ANT Path

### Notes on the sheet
- (near U2) For U2 see Replacement Plan
  Skyworks SKY66500-11
- (near U2) PB14
- (near U2) PA9

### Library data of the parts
C25 C33 = MCD-02620: Capacitor, MLCC, 2.2nF, 50V, X7R, +/-10%, 0402, T=0.5mm; Part_Preference: Recommended; Manufacturer: YAGEO; Manufacturer_Part_Number: CC0402KRX7R9BB222; Order_Code_RS: 199-2257; Component_Country_Of_Origin: China; ShowFields: YES; ID: 4726
C27 = MCD-05030: Capacitor, MLCC, 4.7uF, 6V3, X6R, +/-20%, 0603, T=0.5mm; Part_Preference: Recommended; Manufacturer: MURATA; Manufacturer_Part_Number: GRM185C80J475ME11; Component_Country_Of_Origin: Japan, China, Philippines, Singapore,Thailand; ShowFields: YES; ID: 7146
C28 = MCD-03234: Capacitor, MLCC, 1nF, 50V, C0G/NP0, 5%, 0402, T=0.5mm; Part_Preference: Recommended; Manufacturer: MURATA; Manufacturer_Part_Number: GRM1555C1H102JA01; Order_Code_RS: 276-3731P; Component_Country_Of_Origin: China, Japan; ShowFields: YES; ID: 5350
C29 C39 = MCD-05027: Capacitor, MLCC, 1uF, 6V3, X5R , +/-10%, 0402, T=0.5mm; Part_Preference: Recommended; Manufacturer: MURATA; Manufacturer_Part_Number: GRT155R60J105KE01; Component_Country_Of_Origin: Unknown; ShowFields: YES; ID: 7143
C30 = MCD-00205: as C7 on sheet RF
C31 = MCD-05029: Capacitor, MLCC, 4.7nF, 50V, X7R,  +/-10%, 0402, T=0.5mm; Part_Preference: Recommended; Manufacturer: MURATA; Manufacturer_Part_Number: GRM155R71H472KA01; Component_Country_Of_Origin: Japan, China, Philippines, Singapore, Thailand; ShowFields: YES; ID: 7145
C32 = MCD-04794: Capacitor, MLCC, 68pF, 50V, C0G, 5%, 0402, T=0.5mm; Part_Preference: Recommended; Manufacturer: MURATA; Manufacturer_Part_Number: GRM1555C1H680JA01; Component_Country_Of_Origin: Japan, China, Philippines, Singapore, Thailand; ShowFields: YES; ID: 6910
C34 = GRM1555C1H330GA01D: Internal_Part_Number: MCD-05025; Part_Preference: Recommended
C35 C40 = MCD-03948: as C4 on sheet RF
C36 = MCD-04802: Capacitor, MLCC, 18pF, 50V, C0G, 5%, 0402, T=0.5mm; Part_Preference: Recommended; Manufacturer: MURATA; Manufacturer_Part_Number: GJM1555C1H180JB01; Component_Country_Of_Origin: Japan, Singapore; ShowFields: YES; ID: 6918
C37 = MCD-03431: Capacitor, MLCC, 4.7uF, 10V, X5R, +/-20%, 0402, T=0.5mm; Part_Preference: Recommended; Manufacturer: MURATA; Manufacturer_Part_Number: GRM155R61A475MEAA; Order_Code_RS: 172-6870; Component_Country_Of_Origin: China, Japan, Philippines, Singapore; ShowFields: YES; ID: 5547
C38 = MCD-03431: Part_Preference: Recommended; Manufacturer: MURATA; Order_Code_RS: 172-6870; ShowFields: YES; ID: 5547
L11 = 36501J6N8JTDG: Internal_Part_Number: MCD-05018; Part_Preference: Recommended
L12 = LQG15HN3N9S02D: Internal_Part_Number: MCD-05016; Part_Preference: Recommended
L13 = 36501J27NJTDG: Internal_Part_Number: MCD-05023; Part_Preference: Recommended
L14 = LQG15HN12NJ02D: Internal_Part_Number: MCD-05019; Part_Preference: Recommended
L15 = 0603CS-12NXJRW: Internal_Part_Number: MCD-05020; Part_Preference: Recommended
L16 = CW160808-47NJ: Internal_Part_Number: MCD-05024; Part_Preference: Recommended
L17 = LQG15HN4N7S02D: Internal_Part_Number: MCD-05017; Part_Preference: Recommended
L19 = MCD-01766
L20 = MCD-05015: Ferrite Bead, 600R @ 100MHz, 0A2, 0R65, 0402, T=0.5mm; Part_Type: Inductor; Part_Preference: Recommended; Manufacturer: MURATA; Manufacturer_Part_Number: BLM15BD601SN1D; Order_Code_RS: 724-1270; Component_Country_Of_Origin: Japan, Thailand; ShowFields: YES; ID: 7131
L21 = LQG15HN27NJ02D: Internal_Part_Number: MCD-05022; Part_Preference: Recommended
R9 = MCD-00052: as R1 on sheet RF
U2 = SKY66121-11: 169 to 170 MHz Transmit / Receive Front-End  Module for 27 dBm (no BYPASS funct); Manufacturer: Skyworks

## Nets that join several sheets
GND: MCU_IOs (28 pins), RF (26 pins), Supply (14 pins), FEM (18 pins)
VDD: MCU_IOs (C24.2 CN1.32), RF (C7.2 X2.4), Supply (10 pins)
VDD_FEM: MCU_IOs (CN1.2), FEM (5 pins)
VFBSD: RF (C14.2 C15.2 L8.1), Supply (C22.2 C23.1 L10.1 U1.40)
ANT Path: RF (C2.2 R1.2 R11.1), FEM (C38.2 R9.2)
CSD: MCU_IOs (SB11.2 U1.11), FEM (U2.1)
CTX: MCU_IOs (SB20.1 U1.19), FEM (U2.3)
GPIO5/SWDIO: MCU_IOs (CN1.13 U1.1), Supply (R3.2)
GPIO6/SWCLK: MCU_IOs (CN1.15 U1.2), Supply (R4.2)
GPIO23/VCP1_RX: MCU_IOs (CN1.45 SB14.1), Supply (R7.1)
GPIO24/VCP1_TX: MCU_IOs (CN1.47 SB16.1), Supply (R6.2)
NRST: MCU_IOs (C20.2 CN1.12 U1.36), Supply (R5.2)
RX Path: RF (C10.2 L6.2), FEM (C25.1)
TCXO_EN: MCU_IOs (U1.8), RF (X2.1)
TX Path: RF (C5.2), FEM (C40.2 L21.1)

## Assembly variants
169_27dBm: not fitted C1 C2 C6 C10 C12 C19 C24 C26 C37 C38 CN3 L3 L4 L19 R1 R3 R4 R5 R6 R7 R8 SB2 SB3 SB4 SB6 SB9 SB11 SB17 SB20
